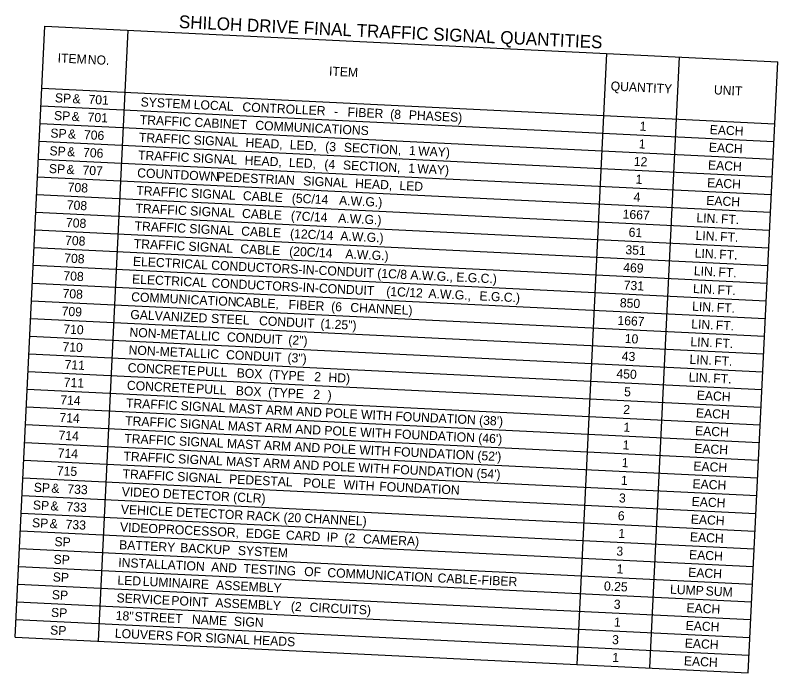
# Model space of a CAD drawing. Extents: x 661030 to 662601, y 642184 to 643065.
# Drawn here: x 661393.3 to 661596.3, y 642791 to 642966.1 of the extents above; entities that cross this region are included whole.
import ezdxf

# ---------------------------------------------------------------- set-up
doc = ezdxf.new("R2010")
doc.units = 0
doc.layers.add('R_Dimension', color=7, linetype='Continuous')

msp = doc.modelspace()

# ---------------------------------------------------------------- linework, layer by layer
at = {"layer": 'R_Dimension'}
for p, q in [((661393.35, 642800.47), (661401.25, 642963.21)), ((661401.25, 642963.21), (661596.34, 642953.74)), ((661415.52, 642799.4), (661423.42, 642962.13)), ((661542.92, 642793.21), (661550.82, 642955.95)), ((661562.26, 642792.27), (661570.16, 642955.01)), ((661588.44, 642791), (661596.34, 642953.74)), ((661400.45, 642946.7), (661595.54, 642937.23)), ((661400.22, 642941.98), (661595.31, 642932.51)), ((661399.99, 642937.27), (661595.08, 642927.79)), ((661399.76, 642932.55), (661594.85, 642923.08)), ((661399.53, 642927.83), (661594.62, 642918.36)), ((661399.3, 642923.11), (661594.39, 642913.64)), ((661399.07, 642918.4), (661594.16, 642908.92)), ((661398.84, 642913.68), (661593.93, 642904.21)), ((661398.61, 642908.96), (661593.7, 642899.49)), ((661398.38, 642904.25), (661593.48, 642894.77)), ((661398.16, 642899.53), (661593.25, 642890.06)), ((661397.93, 642894.81), (661593.02, 642885.34)), ((661397.7, 642890.1), (661592.79, 642880.62)), ((661397.47, 642885.38), (661592.56, 642875.91)), ((661397.24, 642880.66), (661592.33, 642871.19)), ((661397.01, 642875.94), (661592.1, 642866.47)), ((661396.78, 642871.23), (661591.87, 642861.75)), ((661396.55, 642866.51), (661591.64, 642857.04)), ((661396.32, 642861.79), (661591.41, 642852.32)), ((661396.09, 642857.08), (661591.18, 642847.6)), ((661395.86, 642852.36), (661590.96, 642842.89)), ((661395.64, 642847.64), (661590.73, 642838.17)), ((661395.41, 642842.93), (661590.5, 642833.45)), ((661395.18, 642838.21), (661590.27, 642828.74)), ((661394.95, 642833.49), (661590.04, 642824.02)), ((661394.72, 642828.77), (661589.81, 642819.3)), ((661394.49, 642824.06), (661589.58, 642814.58)), ((661394.26, 642819.34), (661589.35, 642809.87)), ((661394.03, 642814.62), (661589.12, 642805.15)), ((661393.8, 642809.91), (661588.89, 642800.43)), ((661393.57, 642805.19), (661588.67, 642795.72)), ((661393.35, 642800.47), (661588.44, 642791))]:
    msp.add_line(p, q, dxfattribs=at)

# ---------------------------------------------------------------- texts
for s, height, p in [('SHILOH DRIVE FINAL TRAFFIC SIGNAL QUANTITIES', 3.3906, (661436.85, 642962.74)), ('ITEM', 2.422, (661404.59, 642953.56)), (' NO.', 2.422, (661411.71, 642953.21)), ('ITEM', 2.422, (661476.83, 642950.05)), ('QUANTITY', 2.422, (661551.81, 642946.1)), ('UNIT', 2.422, (661579.29, 642945.08)), ('SP', 2.422, (661403.86, 642942.96)), (' &', 2.422, (661407.65, 642942.77)), (' 701', 2.422, (661411.9, 642942.57)), ('SYSTEM', 2.422, (661426.69, 642941.85)), (' LOCAL', 2.422, (661439.91, 642941.21)), (' CONTROLLER', 2.4218, (661452.88, 642940.58)), ('SP', 2.422, (661403.63, 642938.24)), (' &', 2.422, (661407.42, 642938.06)), (' 701', 2.422, (661411.67, 642937.85)), (' -', 2.422, (661477.26, 642939.39)), (' FIBER', 2.422, (661480.86, 642939.22)), (' (8', 2.422, (661492.21, 642938.67)), (' PHASES)', 2.422, (661497.18, 642938.43)), ('TRAFFIC', 2.422, (661426.46, 642937.13)), (' CABINET', 2.422, (661440.12, 642936.47)), (' COMMUNICATIONS', 2.4218, (661456.31, 642935.68)), ('1', 2.42, (661559.51, 642935.4)), ('EACH', 2.422, (661578.18, 642934.49)), ('SP', 2.422, (661402.65, 642933.56)), (' &', 2.422, (661406.44, 642933.38)), (' 706', 2.422, (661410.69, 642933.17)), ('TRAFFIC', 2.422, (661426.23, 642932.42)), (' SIGNAL', 2.422, (661439.89, 642931.75)), (' HEAD,', 2.422, (661453.7, 642931.08)), (' LED,', 2.422, (661465.49, 642930.51)), (' (3', 2.422, (661474.91, 642930.05)), (' SECTION,', 2.422, (661479.89, 642929.81)), ('1', 2.42, (661559.29, 642930.68)), ('EACH', 2.422, (661577.95, 642929.78)), ('SP', 2.422, (661402.42, 642928.84)), (' &', 2.422, (661406.21, 642928.66)), (' 706', 2.422, (661410.46, 642928.45)), ('TRAFFIC', 2.422, (661426, 642927.7)), (' 1', 2.422, (661497.24, 642928.97)), (' WAY)', 2.422, (661499.66, 642928.85)), (' SIGNAL', 2.422, (661439.66, 642927.04)), (' HEAD,', 2.422, (661453.47, 642926.36)), (' LED,', 2.422, (661465.26, 642925.79)), ('12', 2.422, (661557.97, 642926.02)), ('SP', 2.422, (661402.26, 642924.12)), (' &', 2.422, (661406.05, 642923.94)), (' 707', 2.422, (661410.3, 642923.73)), (' (4', 2.422, (661474.69, 642925.33)), (' SECTION,', 2.422, (661479.66, 642925.09)), (' 1', 2.422, (661497.01, 642924.25)), (' WAY)', 2.422, (661499.43, 642924.13)), ('EACH', 2.422, (661577.72, 642925.06)), ('COUNTDOWN', 2.422, (661425.77, 642922.98)), (' PEDESTRIAN', 2.4218, (661446.13, 642921.99)), (' SIGNAL', 2.422, (661469.07, 642920.88)), (' HEAD,', 2.422, (661482.88, 642920.21)), (' LED', 2.422, (661494.67, 642919.64)), ('1', 2.42, (661558.43, 642921.27)), ('EACH', 2.422, (661577.49, 642920.34)), ('708', 2.422, (661407.26, 642919.15)), ('TRAFFIC', 2.422, (661425.54, 642918.26)), (' SIGNAL', 2.422, (661439.2, 642917.6)), (' CABLE', 2.422, (661453.01, 642916.93)), (' (5C/14', 2.422, (661466.02, 642916.3)), (' A.W.G.)', 2.422, (661478.61, 642915.69)), ('4', 2.42, (661557.91, 642916.56)), ('EACH', 2.422, (661577.26, 642915.62)), ('708', 2.422, (661407.03, 642914.43)), ('TRAFFIC', 2.422, (661425.31, 642913.55)), (' SIGNAL', 2.422, (661438.97, 642912.88)), (' CABLE', 2.422, (661452.78, 642912.21)), (' (7C/14', 2.422, (661465.79, 642911.58)), ('1667', 2.422, (661555, 642911.98)), ('708', 2.422, (661406.8, 642909.72)), (' A.W.G.)', 2.422, (661478.38, 642910.97)), ('LIN.', 2.422, (661574.64, 642911.02)), (' FT.', 2.422, (661580.28, 642910.75)), ('TRAFFIC', 2.422, (661425.08, 642908.83)), (' SIGNAL', 2.422, (661438.74, 642908.17)), (' CABLE', 2.422, (661452.55, 642907.5)), (' (12C/14', 2.422, (661465.56, 642906.86)), (' A.W.G.)', 2.422, (661478.95, 642906.21)), ('61', 2.422, (661556.6, 642907.17)), ('LIN.', 2.422, (661574.41, 642906.31)), (' FT.', 2.422, (661580.05, 642906.03)), ('708', 2.422, (661406.57, 642905)), ('TRAFFIC', 2.422, (661424.86, 642904.11)), (' SIGNAL', 2.422, (661438.51, 642903.45)), (' CABLE', 2.422, (661452.32, 642902.78)), (' (20C/14', 2.422, (661465.33, 642902.15)), (' A.W.G.)', 2.422, (661480.28, 642901.42)), ('351', 2.422, (661555.74, 642902.49)), ('LIN.', 2.422, (661574.18, 642901.59)), (' FT.', 2.422, (661579.82, 642901.32)), ('708', 2.422, (661406.34, 642900.28)), ('ELECTRICAL CONDUCTORS-IN-CONDUIT (1C/8 A.W.G., E.G.C.)', 2.4218, (661424.63, 642899.4)), ('469', 2.422, (661555.16, 642897.79)), ('708', 2.422, (661406.12, 642895.57)), ('LIN.', 2.422, (661573.96, 642896.87)), (' FT.', 2.422, (661579.59, 642896.6)), ('ELECTRICAL', 2.422, (661424.4, 642894.68)), (' CONDUCTORS-IN-CONDUIT', 2.4218, (661444.66, 642893.69)), (' (1C/12', 2.422, (661491.18, 642891.44)), ('731', 2.422, (661555.28, 642893.05)), ('LIN.', 2.422, (661573.73, 642892.16)), (' FT.', 2.422, (661579.36, 642891.88)), ('708', 2.422, (661405.89, 642890.85)), ('COMMUNICATION', 2.4218, (661424.17, 642889.96)), (' A.W.G.,', 2.422, (661502.4, 642890.89)), (' E.G.C.)', 2.422, (661515.98, 642890.23)), (' CABLE,', 2.422, (661451.08, 642888.66)), (' FIBER', 2.422, (661465.16, 642887.97)), (' (6', 2.422, (661476.51, 642887.42)), (' CHANNEL)', 2.422, (661481.61, 642887.17)), ('850', 2.422, (661554.26, 642888.37)), ('LIN.', 2.422, (661573.5, 642887.44)), (' FT.', 2.422, (661579.14, 642887.17)), ('709', 2.422, (661405.65, 642886.13)), ('GALVANIZED', 2.422, (661423.94, 642885.25)), (' STEEL', 2.422, (661444.53, 642884.25)), (' CONDUIT', 2.422, (661457.31, 642883.62)), ('1667', 2.422, (661553.62, 642883.68)), ('710', 2.422, (661406.1, 642881.38)), (' (1.25")', 2.422, (661473.65, 642882.83)), ('LIN.', 2.422, (661573.27, 642882.72)), (' FT.', 2.422, (661578.91, 642882.45)), ('NON-METALLIC', 2.4218, (661423.71, 642880.53)), (' CONDUIT', 2.422, (661448.76, 642879.31)), (' (2")', 2.422, (661465.1, 642878.52)), ('10', 2.422, (661555.57, 642878.85)), ('LIN.', 2.422, (661573.04, 642878)), (' FT.', 2.422, (661578.68, 642877.73)), ('710', 2.422, (661405.87, 642876.67)), ('NON-METALLIC', 2.4218, (661423.48, 642875.81)), (' CONDUIT', 2.422, (661448.53, 642874.59)), (' (3")', 2.422, (661464.87, 642873.8)), ('43', 2.422, (661554.76, 642874.16)), ('LIN.', 2.422, (661572.81, 642873.29)), (' FT.', 2.422, (661578.45, 642873.01)), ('711', 2.422, (661406.44, 642871.91)), ('CONCRETE', 2.422, (661423.25, 642871.09)), (' PULL', 2.422, (661440.78, 642870.24)), (' BOX', 2.422, (661451.35, 642869.73)), (' (TYPE', 2.422, (661459.94, 642869.31)), ('450', 2.422, (661553.35, 642869.5)), ('711', 2.422, (661406.21, 642867.19)), (' 2', 2.422, (661471.99, 642868.73)), (' HD)', 2.422, (661475.78, 642868.54)), ('LIN.', 2.422, (661572.58, 642868.57)), (' FT.', 2.422, (661578.22, 642868.3)), ('CONCRETE', 2.422, (661423.02, 642866.38)), (' PULL', 2.422, (661440.55, 642865.53)), (' BOX', 2.422, (661451.12, 642865.01)), (' (TYPE', 2.422, (661459.71, 642864.6)), (' 2', 2.422, (661471.76, 642864.01)), (' )', 2.422, (661475.56, 642863.83)), ('5', 2.42, (661555.39, 642864.68)), ('EACH', 2.422, (661574.74, 642863.74)), ('714', 2.422, (661405.29, 642862.51)), ("TRAFFIC SIGNAL MAST ARM AND POLE WITH FOUNDATION (38')", 2.4218, (661422.79, 642861.66)), ('2', 2.42, (661555.16, 642859.96)), ('EACH', 2.422, (661574.51, 642859.02)), ('714', 2.422, (661405.06, 642857.79)), ("TRAFFIC SIGNAL MAST ARM AND POLE WITH FOUNDATION (46')", 2.4218, (661422.57, 642856.94)), ('1', 2.42, (661555.22, 642855.23)), ('714', 2.422, (661404.83, 642853.08)), ('EACH', 2.422, (661574.28, 642854.3)), ("TRAFFIC SIGNAL MAST ARM AND POLE WITH FOUNDATION (52')", 2.4218, (661422.34, 642852.23)), ('1', 2.42, (661554.99, 642850.51)), ('EACH', 2.422, (661574.06, 642849.59)), ('714', 2.422, (661404.61, 642848.36)), ("TRAFFIC SIGNAL MAST ARM AND POLE WITH FOUNDATION (54')", 2.4218, (661422.11, 642847.51)), ('1', 2.42, (661554.76, 642845.8)), ('EACH', 2.422, (661573.83, 642844.87)), ('715', 2.422, (661404.38, 642843.64)), ('TRAFFIC', 2.422, (661421.88, 642842.79)), (' SIGNAL', 2.422, (661435.53, 642842.13)), (' PEDESTAL', 2.422, (661449.34, 642841.46)), (' POLE', 2.422, (661469.06, 642840.5)), ('1', 2.42, (661554.53, 642841.08)), ('SP', 2.422, (661398.23, 642839.21)), (' &', 2.422, (661402.02, 642839.03)), (' 733', 2.422, (661406.27, 642838.82)), (' WITH', 2.422, (661479.78, 642839.98)), (' FOUNDATION', 2.4218, (661489.32, 642839.52)), ('EACH', 2.422, (661573.6, 642840.15)), ('VIDEO DETECTOR (CLR)', 2.4218, (661421.65, 642838.08)), ('3', 2.42, (661554.02, 642836.38)), ('SP', 2.422, (661398, 642834.49)), (' &', 2.422, (661401.79, 642834.31)), ('EACH', 2.422, (661573.37, 642835.44)), (' 733', 2.422, (661406.04, 642834.1)), ('VEHICLE DETECTOR RACK (20 CHANNEL)', 2.4218, (661421.42, 642833.36)), ('6', 2.42, (661553.72, 642831.66)), ('EACH', 2.422, (661573.14, 642830.72)), ('SP', 2.422, (661397.77, 642829.78)), (' &', 2.422, (661401.57, 642829.59)), (' 733', 2.422, (661405.81, 642829.39)), ('VIDEO', 2.422, (661421.19, 642828.64)), (' PROCESSOR,', 2.4218, (661430.39, 642828.19)), (' EDGE', 2.422, (661453.8, 642827.06)), (' CARD', 2.422, (661464.45, 642826.54)), ('1', 2.42, (661553.85, 642826.93)), ('SP', 2.422, (661403.74, 642824.76)), (' IP', 2.422, (661475.3, 642826.01)), (' (2', 2.422, (661480.03, 642825.78)), (' CAMERA)', 2.422, (661485, 642825.54)), ('EACH', 2.422, (661572.91, 642826)), ('BATTERY', 2.422, (661420.96, 642823.92)), (' BACKUP', 2.422, (661436.31, 642823.18)), (' SYSTEM', 2.422, (661451.67, 642822.43)), ('3', 2.42, (661553.33, 642822.22)), ('SP', 2.422, (661403.51, 642820.04)), ('EACH', 2.422, (661572.68, 642821.28)), ('INSTALLATION', 2.4218, (661420.73, 642819.21)), (' AND', 2.422, (661444.56, 642818.05)), (' TESTING', 2.422, (661453.13, 642817.63)), (' OF', 2.422, (661469.32, 642816.85)), (' COMMUNICATION', 2.4218, (661475.49, 642816.55)), ('1', 2.42, (661553.39, 642817.49)), ('EACH', 2.422, (661572.45, 642816.57)), ('SP', 2.422, (661403.28, 642815.33)), ('LED', 2.422, (661420.5, 642814.49)), (' LUMINAIRE', 2.422, (661426.35, 642814.21)), (' CABLE-FIBER', 2.4218, (661504.83, 642815.12)), (' ASSEMBLY', 2.422, (661445.87, 642813.26)), ('0.25', 2.422, (661550.02, 642812.93)), ('LUMP', 2.422, (661567.61, 642812.07)), ('SP', 2.422, (661403.05, 642810.61)), (' SUM', 2.422, (661576.2, 642811.66)), ('SERVICE', 2.422, (661420.27, 642809.77)), (' POINT', 2.422, (661433.95, 642809.11)), (' ASSEMBLY', 2.422, (661445.68, 642808.54)), ('3', 2.42, (661552.64, 642808.07)), ('SP', 2.422, (661402.82, 642805.89)), (' (2', 2.422, (661465.78, 642807.56)), (' CIRCUITS)', 2.422, (661470.75, 642807.32)), ('EACH', 2.422, (661571.99, 642807.13)), ('18"', 2.422, (661420.05, 642805.06)), (' STREET', 2.422, (661424.18, 642804.86)), (' NAME', 2.422, (661439.45, 642804.11)), (' SIGN', 2.422, (661450.6, 642803.57)), ('1', 2.42, (661552.7, 642803.34)), ('EACH', 2.422, (661571.77, 642802.42)), ('SP', 2.422, (661402.59, 642801.18)), ('LOUVERS FOR SIGNAL HEADS', 2.4218, (661419.82, 642800.34)), ('3', 2.42, (661552.19, 642798.64)), ('EACH', 2.422, (661571.54, 642797.7)), ('1', 2.42, (661552.24, 642793.91)), ('EACH', 2.422, (661571.31, 642792.98))]:
    msp.add_text(s, height=height, rotation=357.2199, dxfattribs=at).set_placement(p)

doc.saveas('drawing.dxf')
